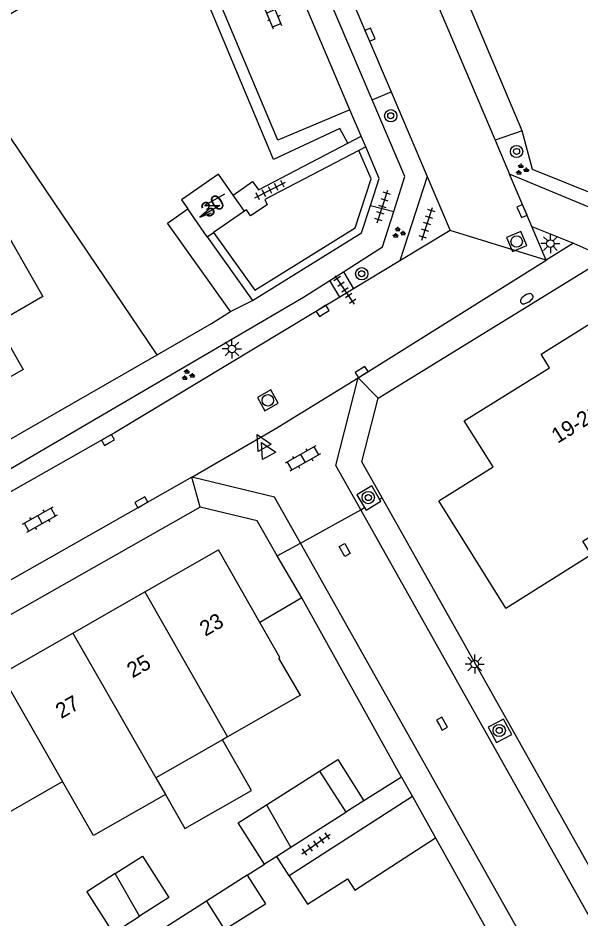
# Model space of a CAD drawing. Extents: x 136000 to 141014, y 402000 to 403500.
# Drawn here: x 137265 to 137301.7, y 402199.5 to 402258.2 of the extents above; entities that cross this region are included whole.
import ezdxf

# ---------------------------------------------------------------- set-up
doc = ezdxf.new("R2010")
doc.units = 0
for name, color, linetype in [('gg-afsc-erfafscheiding', 7, 'Continuous'), ('gg-afsc-muur', 7, 'Continuous'), ('gg-anno-huisnummerreeks BGT', 7, 'Continuous'), ('gg-bbg-bijgebouw', 7, 'Continuous'), ('gg-bbg-gedigitaliseerde bebouwing', 7, 'Continuous'), ('gg-bbg-gedigitaliseerde bijgebouw', 7, 'Continuous'), ('gg-bbg-hoofdgebouw', 7, 'Continuous'), ('gg-bbg-luifel en loopbrug', 7, 'Continuous'), ('gg-bbg-tussenscheiding', 7, 'Continuous'), ('gg-knt-verharding', 7, 'Continuous'), ('gg-knt-verharding nz', 7, 'Continuous'), ('gt-grn-groengrens', 7, 'Continuous'), ('gt-grn-weggrens', 7, 'Continuous'), ('gt-symb-boom', 7, 'Continuous'), ('gt-symb-brandkraan', 7, 'Continuous'), ('gt-symb-groenvak', 7, 'Continuous'), ('gt-symb-klinker verharding', 7, 'Continuous'), ('gt-symb-kolk', 7, 'Continuous'), ('gt-symb-kolk center center', 7, 'Continuous'), ('gt-symb-lichtmast', 7, 'Continuous'), ('gt-symb-rioolschacht', 7, 'Continuous'), ('gt-symb-tegel verharding', 7, 'Continuous'), ('gt-symb-trafo symbool', 7, 'Continuous'), ('gt-symb-waterafsluiter', 7, 'Continuous')]:
    doc.layers.add(name, color=color, linetype=linetype)

# ---------------------------------------------------------------- blocks, each defined once
blk = doc.blocks.new('gt0-GRVAK')
at = {"layer": 'gt-symb-groenvak'}
for p, q in [((-0.11, 0.189), (-0.228, 0.24)), ((-0.182, 0.153), (0.088, 0.153)), ((-0.091, 0.211), (-0.156, 0.322)), ((-0.047, 0.214), (-0.047, 0.393)), ((-0.004, 0.211), (0.061, 0.322)), ((0.015, 0.189), (0.133, 0.24)), ((0.262, -0.052), (0.197, 0.059)), ((0.305, -0.049), (0.305, 0.13)), ((0.349, -0.052), (0.414, 0.059)), ((-0.245, -0.228), (-0.363, -0.177)), ((-0.318, -0.264), (-0.047, -0.264)), ((-0.226, -0.206), (-0.291, -0.095)), ((-0.183, -0.203), (-0.183, -0.024)), ((-0.139, -0.206), (-0.074, -0.095)), ((-0.12, -0.228), (-0.002, -0.177)), ((0.243, -0.074), (0.125, -0.023)), ((0.17, -0.11), (0.441, -0.11)), ((0.368, -0.074), (0.486, -0.023))]:
    blk.add_line(p, q, dxfattribs=at)
blk = doc.blocks.new('gt0-TEG1')
at = {"layer": 'gt-symb-tegel verharding'}
for p, q in [((-1.125, 0), (1.125, 0)), ((-0.9, -0.25), (-0.9, 0.25)), ((-0.45, -0.25), (-0.45, 0.25)), ((0, -0.25), (0, 0.25)), ((0.45, -0.25), (0.45, 0.25)), ((0.9, -0.25), (0.9, 0.25))]:
    blk.add_line(p, q, dxfattribs=at)
blk = doc.blocks.new('gt0-BOOM')
at = {"layer": 'gt-symb-boom'}
for radius in [0.4, 0.2]:
    blk.add_circle((0, 0), radius, dxfattribs=at)
blk = doc.blocks.new('gt0-RS')
at = {"layer": 'gt-symb-rioolschacht'}
blk.add_lwpolyline([(-0.5, -0.5), (0.5, -0.5), (0.5, 0.5), (-0.5, 0.5)], close=True, dxfattribs=at)
blk.add_circle((0, 0), 0.375, dxfattribs=at)
blk = doc.blocks.new('gt0-KOLK')
at = {"layer": 'gt-symb-kolk'}
blk.add_lwpolyline([(0, 0), (0.375, 0), (0.375, 0.4), (-0.375, 0.4), (-0.375, 0), (0, 0)], dxfattribs=at)
blk = doc.blocks.new('gt0-BR')
at = {"layer": 'gt-symb-brandkraan'}
for centre, radius, start, end in [((-0.244, 0), 0.206, 107.56694, 252.43307), ((0.599, -2.664), 3, 106.89205, 107.56694), ((0, -0.691), 0.938, 73.10799, 106.89205), ((-0.599, -2.664), 3, 72.43309, 73.10799), ((0.244, 0), 0.206, 287.56695, 72.43309), ((0.599, 2.664), 3, 252.43307, 253.10797), ((0, 0.691), 0.938, 253.10797, 286.89206), ((-0.599, 2.664), 3, 286.89206, 287.56695)]:
    blk.add_arc(centre, radius, start, end, dxfattribs=at)
blk = doc.blocks.new('gt0-LMAST')
at = {"layer": 'gt-symb-lichtmast'}
for p, q in [((-0.005, 0.246), (-0.005, 0.621)), ((-0.182, 0.173), (-0.447, 0.438)), ((0.172, 0.173), (0.437, 0.438)), ((-0.255, -0.004), (-0.63, -0.004)), ((-0.182, -0.181), (-0.447, -0.446)), ((-0.005, -0.254), (-0.005, -0.629)), ((0.437, -0.446), (0.172, -0.181)), ((0.245, -0.004), (0.62, -0.004))]:
    blk.add_line(p, q, dxfattribs=at)
blk.add_circle((-0.005, -0.004), 0.25, dxfattribs=at)
blk = doc.blocks.new('gt0-KOLKCC')
at = {"layer": 'gt-symb-kolk center center'}
blk.add_lwpolyline([(-0.375, 0.2), (0.375, 0.2), (0.375, -0.2), (-0.375, -0.2)], close=True, dxfattribs=at)
blk = doc.blocks.new('gt0-KL1')
at = {"layer": 'gt-symb-klinker verharding'}
for p, q in [((-1.15, 0.3), (1.15, 0.3)), ((-1, -0.3), (-1, 0.3)), ((-0.5, 0.3), (-0.5, 0.45)), ((0, -0.3), (0, 0.3)), ((0.5, 0.3), (0.5, 0.45)), ((1, -0.3), (1, 0.3)), ((-1.15, -0.3), (1.15, -0.3)), ((-0.5, -0.45), (-0.5, -0.3)), ((0.5, -0.45), (0.5, -0.3))]:
    blk.add_line(p, q, dxfattribs=at)
blk = doc.blocks.new('gt0-HSP')
at = {"layer": 'gt-symb-trafo symbool'}
for points in [[(0.771, 0.746), (-0.529, -0.004), (0.471, -0.004), (-0.829, -0.754)], [(-0.217, -0.24), (-0.829, -0.754), (-0.077, -0.48)]]:
    blk.add_lwpolyline(points, dxfattribs=at)
blk = doc.blocks.new('gt0-WAFSL')
at = {"layer": 'gt-symb-waterafsluiter'}
for p, q in [((-0.5, -0.333), (0, 0.667)), ((0, 0.667), (0.5, -0.333)), ((0.5, -0.333), (-0.5, -0.333))]:
    blk.add_line(p, q, dxfattribs=at)

msp = doc.modelspace()

# ---------------------------------------------------------------- linework, layer by layer
at = {"layer": 'gg-afsc-erfafscheiding'}
for p, q in [((137290.03, 402208.679), (137287.569, 402207.129)), ((137290.03, 402208.679), (137290.735, 402207.413)), ((137282.702, 402202.222), (137281.887, 402203.496))]:
    msp.add_line(p, q, dxfattribs=at)
for points in [[(137274.094, 402236.239), (137260.587, 402256.216), (137272.524, 402263.213), (137236.791, 402313.855)], [(137309.532, 402243.911), (137298.572, 402248.337), (137297.888, 402250.859)]]:
    msp.add_lwpolyline(points, dxfattribs=at)
at = {"layer": 'gg-afsc-muur'}
for p, q in [((137283.52, 402220.376), (137280.792, 402218.757)), ((137290.03, 402208.679), (137283.52, 402220.376)), ((137292.23, 402204.722), (137295.922, 402198.102)), ((137279.968, 402202.271), (137281.089, 402202.987))]:
    msp.add_line(p, q, dxfattribs=at)
at = {"layer": 'gg-bbg-bijgebouw'}
for p, q in [((137281.217, 402206.865), (137284.676, 402209.073)), ((137284.676, 402209.073), (137286.389, 402206.386)), ((137290.735, 402207.413), (137282.702, 402202.222)), ((137290.735, 402207.413), (137292.23, 402204.722)), ((137282.805, 402204.082), (137281.887, 402203.496)), ((137281.887, 402203.496), (137281.089, 402202.987)), ((137279.968, 402202.271), (137281.153, 402200.394))]:
    msp.add_line(p, q, dxfattribs=at)
for points in [[(137281.089, 402202.987), (137279.368, 402205.685), (137281.217, 402206.865)], [(137286.389, 402206.386), (137286.397, 402206.374), (137282.805, 402204.082)], [(137282.702, 402202.222), (137283.883, 402200.373), (137286.493, 402202.037), (137286.97, 402201.289), (137292.23, 402204.722)]]:
    msp.add_lwpolyline(points, dxfattribs=at)
at = {"layer": 'gg-bbg-gedigitaliseerde bebouwing'}
for p, q in [((137283.443, 402214.014), (137278.687, 402211.294)), ((137278.349, 402211.101), (137274.009, 402208.619)), ((137278.687, 402211.294), (137278.349, 402211.101)), ((137274.009, 402208.619), (137274.624, 402207.543)), ((137263.078, 402205.612), (137267.921, 402208.387))]:
    msp.add_line(p, q, dxfattribs=at)
msp.add_lwpolyline([(137274.624, 402207.543), (137269.936, 402204.863), (137267.921, 402208.387)], dxfattribs=at)
at = {"layer": 'gg-bbg-gedigitaliseerde bijgebouw'}
for p, q in [((137279.968, 402202.271), (137277.3, 402200.585)), ((137277.3, 402200.585), (137274.65, 402198.89)), ((137278.488, 402198.728), (137281.153, 402200.394))]:
    msp.add_line(p, q, dxfattribs=at)
for points in [[(137271.355, 402202.38), (137273.124, 402203.509), (137274.844, 402200.813), (137272.944, 402199.6)], [(137271.355, 402202.38), (137269.501, 402201.197), (137271.222, 402198.501), (137272.944, 402199.6)]]:
    msp.add_lwpolyline(points, dxfattribs=at)
at = {"layer": 'gg-bbg-hoofdgebouw'}
for p, q in [((137279.78, 402245.61), (137279.046, 402246.661)), ((137277.36, 402243.93), (137276.081, 402245.772)), ((137279.78, 402245.61), (137277.765, 402244.211)), ((137277.36, 402243.93), (137277.765, 402244.211)), ((137273.284, 402220.758), (137278.089, 402223.505)), ((137280.792, 402218.757), (137278.089, 402223.505)), ((137268.6, 402218.08), (137273.284, 402220.758)), ((137263.913, 402215.4), (137268.6, 402218.08))]:
    msp.add_line(p, q, dxfattribs=at)
for points in [[(137279.046, 402246.661), (137278.09, 402248.03), (137275.68, 402246.35), (137276.081, 402245.772)], [(137263.634, 402245.268), (137266.636, 402240.048), (137263.612, 402238.309), (137265.354, 402235.28), (137255.386, 402229.549), (137249.621, 402239.488)], [(137296.827, 402219.703), (137292.45, 402226.699), (137295.992, 402228.916), (137294.112, 402231.921), (137299.666, 402235.396), (137299.119, 402236.27), (137304.233, 402239.47)], [(137296.827, 402219.703), (137302.398, 402223.193), (137301.853, 402224.064), (137307.686, 402227.719), (137306.908, 402228.961), (137309.706, 402230.714), (137307.953, 402233.513), (137308.537, 402233.878), (137308.595, 402233.785), (137308.865, 402233.955), (137306.816, 402237.227), (137306.545, 402237.057), (137306.609, 402236.956), (137306.034, 402236.596), (137304.233, 402239.47)], [(137283.443, 402214.014), (137282.032, 402216.438), (137282.092, 402216.473), (137280.792, 402218.757)]]:
    msp.add_lwpolyline(points, dxfattribs=at)
at = {"layer": 'gg-bbg-luifel en loopbrug'}
msp.add_line((137287.569, 402207.129), (137286.389, 402206.386), dxfattribs=at)
for points in [[(137274.624, 402207.543), (137275.895, 402205.32), (137280.236, 402207.802), (137278.349, 402211.101)], [(137284.676, 402209.073), (137285.865, 402209.825), (137287.569, 402207.129)]]:
    msp.add_lwpolyline(points, dxfattribs=at)
at = {"layer": 'gg-bbg-tussenscheiding'}
for p, q in [((137273.284, 402220.758), (137278.687, 402211.294)), ((137268.6, 402218.08), (137274.009, 402208.619)), ((137263.913, 402215.4), (137267.921, 402208.387)), ((137281.217, 402206.865), (137282.805, 402204.082)), ((137272.944, 402199.6), (137271.355, 402202.38)), ((137277.3, 402200.585), (137278.488, 402198.728))]:
    msp.add_line(p, q, dxfattribs=at)
at = {"layer": 'gg-knt-verharding'}
for p, q in [((137297.888, 402250.859), (137280.686, 402291.585)), ((137288.109, 402252.87), (137282.206, 402266.76)), ((137283.448, 402267.261), (137289.348, 402253.395)), ((137286.658, 402252.232), (137280.761, 402266.121)), ((137288.109, 402252.87), (137289.348, 402253.395)), ((137289.348, 402253.395), (137291.697, 402247.875)), ((137287.395, 402250.496), (137286.658, 402252.232)), ((137297.888, 402250.859), (137296.123, 402250.25)), ((137286.519, 402250.039), (137287.395, 402250.496)), ((137287.688, 402249.806), (137287.395, 402250.496)), ((137287.688, 402249.806), (137287.25, 402249.577)), ((137296.123, 402250.25), (137297.072, 402248.022)), ((137308.571, 402243.215), (137297.072, 402248.022)), ((137291.697, 402247.875), (137289.917, 402242.37)), ((137291.697, 402247.875), (137293.198, 402244.349)), ((137298.521, 402244.62), (137301.242, 402243.526)), ((137277.36, 402243.93), (137280.316, 402239.789)), ((137293.198, 402244.349), (137289.917, 402242.37)), ((137301.242, 402243.526), (137299.462, 402242.412)), ((137289.917, 402242.37), (137286.885, 402240.542)), ((137288.504, 402233.405), (137302.551, 402242.065)), ((137285.343, 402241.097), (137286.235, 402241.662)), ((137286.235, 402241.662), (137286.885, 402240.542)), ((137285.998, 402240.007), (137285.343, 402241.097)), ((137286.885, 402240.542), (137285.998, 402240.007)), ((137287.188, 402234.725), (137288.504, 402233.405)), ((137276.905, 402226.297), (137276.356, 402228.257)), ((137288.596, 402226.814), (137288.756, 402226.903)), ((137276.905, 402226.297), (137254.831, 402213.772)), ((137287.36, 402226.129), (137287.609, 402226.267)), ((137283.434, 402223.954), (137287.36, 402226.129)), ((137281.907, 402223.108), (137283.434, 402223.954)), ((137283.52, 402220.376), (137281.907, 402223.108))]:
    msp.add_line(p, q, dxfattribs=at)
for points in [[(137286.658, 402252.232), (137281.948, 402250.241), (137276.135, 402264.098), (137280.761, 402266.121)], [(137289.511, 402245.579), (137290.232, 402247.876), (137288.109, 402252.87)], [(137279.046, 402246.661), (137280.302, 402247.537), (137280.705, 402247.005), (137286.519, 402250.039)], [(137287.993, 402245.979), (137288.562, 402247.749), (137287.688, 402249.806)], [(137287.25, 402249.577), (137281.102, 402246.369), (137281.257, 402246.034), (137280.18, 402245.3), (137279.905, 402245.691), (137279.78, 402245.61)], [(137278.862, 402239.056), (137274.765, 402244.823), (137276.081, 402245.772)], [(137280.316, 402239.789), (137287.423, 402244.208), (137287.993, 402245.979)], [(137286.235, 402241.662), (137288.79, 402243.281), (137289.511, 402245.579)], [(137263.108, 402227.995), (137283.621, 402240.006), (137285.343, 402241.097)], [(137285.998, 402240.007), (137271.351, 402231.173), (137263.742, 402226.855)], [(137274.094, 402236.239), (137277.643, 402238.279), (137278.862, 402239.056)], [(137229.32, 402212.214), (137231.192, 402211.578), (137274.094, 402236.239)], [(137276.356, 402228.257), (137281.782, 402231.41), (137287.188, 402234.725)], [(137288.756, 402226.903), (137287.432, 402229.259), (137288.504, 402233.405)], [(137288.596, 402226.814), (137288.077, 402227.687), (137287.111, 402227.105), (137287.609, 402226.267)], [(137287.609, 402226.267), (137287.713, 402226.093), (137288.679, 402226.675), (137288.596, 402226.814)], [(137337.516, 402149.901), (137310.025, 402189.058), (137288.756, 402226.903)], [(137281.907, 402223.108), (137280.613, 402225.408), (137276.905, 402226.297)], [(137295.666, 402211.932), (137296.221, 402210.938), (137297.22, 402211.454), (137296.665, 402212.447), (137295.666, 402211.932)]]:
    msp.add_lwpolyline(points, dxfattribs=at)
at = {"layer": 'gg-knt-verharding nz'}
for p, q in [((137278.89, 402290.822), (137296.123, 402250.25)), ((137298.521, 402244.62), (137297.072, 402248.022)), ((137299.462, 402242.412), (137298.521, 402244.62)), ((137287.188, 402234.725), (137299.462, 402242.412)), ((137276.356, 402228.257), (137236.787, 402205.79))]:
    msp.add_line(p, q, dxfattribs=at)
for points in [[(137287.36, 402226.129), (137285.737, 402229.021), (137287.188, 402234.725)], [(137283.434, 402223.954), (137281.747, 402226.956), (137276.356, 402228.257)], [(137336.186, 402148.941), (137308.182, 402189.032), (137287.36, 402226.129)], [(137300.935, 402189.541), (137301.473, 402191.857), (137283.434, 402223.954)]]:
    msp.add_lwpolyline(points, dxfattribs=at)
at = {"layer": 'gt-grn-groengrens'}
for points in [[(137286.519, 402250.039), (137285.999, 402251), (137281.666, 402248.985), (137275.204, 402264.501), (137279.565, 402266.467), (137268.615, 402292.203), (137269.523, 402292.589)], [(137277.765, 402244.211), (137280.449, 402240.452), (137287.009, 402244.531), (137288.036, 402247.725), (137287.25, 402249.577)]]:
    msp.add_lwpolyline(points, dxfattribs=at)
at = {"layer": 'gt-grn-weggrens'}
for p, q in [((137287.993, 402245.979), (137289.511, 402245.579)), ((137299.462, 402242.412), (137293.198, 402244.349)), ((137301.242, 402243.526), (137303.362, 402242.565)), ((137278.862, 402239.056), (137280.316, 402239.789))]:
    msp.add_line(p, q, dxfattribs=at)

# ---------------------------------------------------------------- block references
at = {"layer": 'gt-symb-boom'}
for p in [(137289.322, 402251.837), (137297.525, 402249.506), (137287.427, 402241.524), (137287.857, 402226.921), (137296.395, 402211.718)]:
    msp.add_blockref('gt0-BOOM', p, dxfattribs=at)
at = {"layer": 'gt-symb-brandkraan', "rotation": 31.877816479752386}
msp.add_blockref('gt0-BR', (137298.189, 402239.894), dxfattribs=at)
at = {"layer": 'gt-symb-groenvak'}
for p in [(137297.86, 402248.322), (137289.827, 402244.199), (137276.08, 402234.909)]:
    msp.add_blockref('gt0-GRVAK', p, dxfattribs=at)
at = {"layer": 'gt-symb-klinker verharding'}
for p, rotation in [((137281.507, 402258.66), 112.76972663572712), ((137283.583, 402229.468), -150.07751301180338), ((137266.449, 402225.483), 29.588607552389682)]:
    msp.add_blockref('gt0-KL1', p, dxfattribs=dict(at, rotation=rotation))
at = {"layer": 'gt-symb-kolk'}
for p, rotation in [((137287.781, 402257.056), -66.92177859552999), ((137297.695, 402245.537), -66.92177859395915), ((137284.99, 402238.934), 32.084361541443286), ((137287.528, 402234.942), 32.084361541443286), ((137270.993, 402230.508), 29.58860755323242), ((137273.157, 402226.441), 29.588607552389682), ((137292.495, 402212.065), -60.71717142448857)]:
    msp.add_blockref('gt0-KOLK', p, dxfattribs=dict(at, rotation=rotation))
at = {"layer": 'gt-symb-kolk center center', "rotation": -61.26910628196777}
msp.add_blockref('gt0-KOLKCC', (137286.322, 402223.503), dxfattribs=at)
at = {"layer": 'gt-symb-lichtmast'}
for p in [(137299.734, 402243.498), (137278.968, 402236.624), (137294.798, 402216.056)]:
    msp.add_blockref('gt0-LMAST', p, dxfattribs=at)
at = {"layer": 'gt-symb-rioolschacht'}
for p, rotation in [((137297.528, 402243.627), -66.92177859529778), ((137281.305, 402233.263), 29.58860754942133)]:
    msp.add_blockref('gt0-RS', p, dxfattribs=dict(at, rotation=rotation))
at = {"layer": 'gt-symb-tegel verharding'}
for p, rotation in [((137281.455, 402246.983), 27.000654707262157), ((137288.787, 402245.913), 72.23567662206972), ((137291.696, 402244.788), 72.23567662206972), ((137286.328, 402240.467), 123.91251258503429), ((137284.444, 402204.309), 35.02487328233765)]:
    msp.add_blockref('gt0-TEG1', p, dxfattribs=dict(at, rotation=rotation))
at = {"layer": 'gt-symb-trafo symbool'}
msp.add_blockref('gt0-HSP', (137277.709, 402245.984), dxfattribs=at)
at = {"layer": 'gt-symb-waterafsluiter', "rotation": 29.74488129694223}
for p in [(137280.935, 402230.454), (137281.233, 402229.933)]:
    msp.add_blockref('gt0-WAFSL', p, dxfattribs=at)

# ---------------------------------------------------------------- texts
at = {"layer": 'gg-anno-huisnummerreeks BGT'}
for s, rotation, p in [('30', 34.9, (137277.377, 402245.125)), ('19-21a', 32, (137300.2, 402230.423)), ('23', 29.7, (137277.229, 402217.831)), ('25', 29.7, (137272.484, 402215.118)), ('27', 29.7, (137267.834, 402212.459))]:
    msp.add_text(s, height=1, rotation=rotation, dxfattribs=at).set_placement(p)

doc.saveas('drawing.dxf')
